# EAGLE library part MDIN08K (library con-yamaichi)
YAMAICHI CONNECTOR
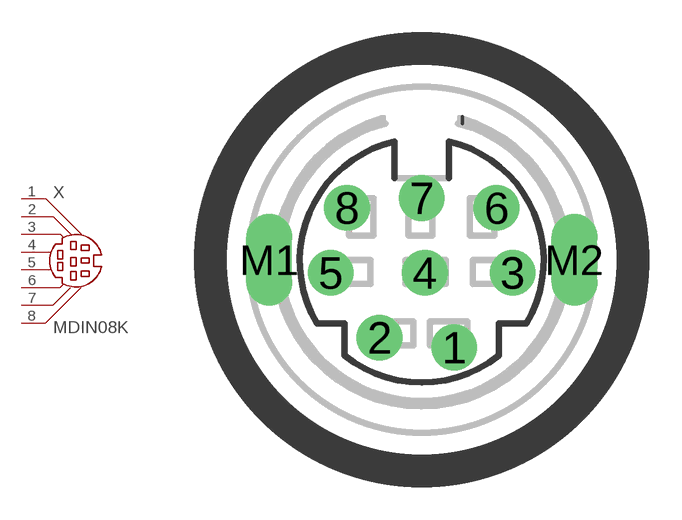
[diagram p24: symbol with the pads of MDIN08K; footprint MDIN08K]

Designator prefix X

## MDIN08K (OC_FARNELL: unknown; OC_NEWARK: unknown)  [MDIN08K]
1  1  pas
2  2  pas
3  3  pas
4  4  pas
5  5  pas
6  6  pas
7  7  pas
8  8  pas

## Footprint MDIN08K (pad centres in mm)
Mini Din YAMAICHI CONNECTOR
drill 0.9 round: 1 1,-2.7; 2 -1.3,-2.4; 3 2.8,-0.4; 4 0.1,-0.4; 5 -2.8,-0.4; 6 2.3,1.6; 7 0,1.9; 8 -2.3,1.6
drill 0.9 long: M1 -4.7,0; M2 4.7,0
